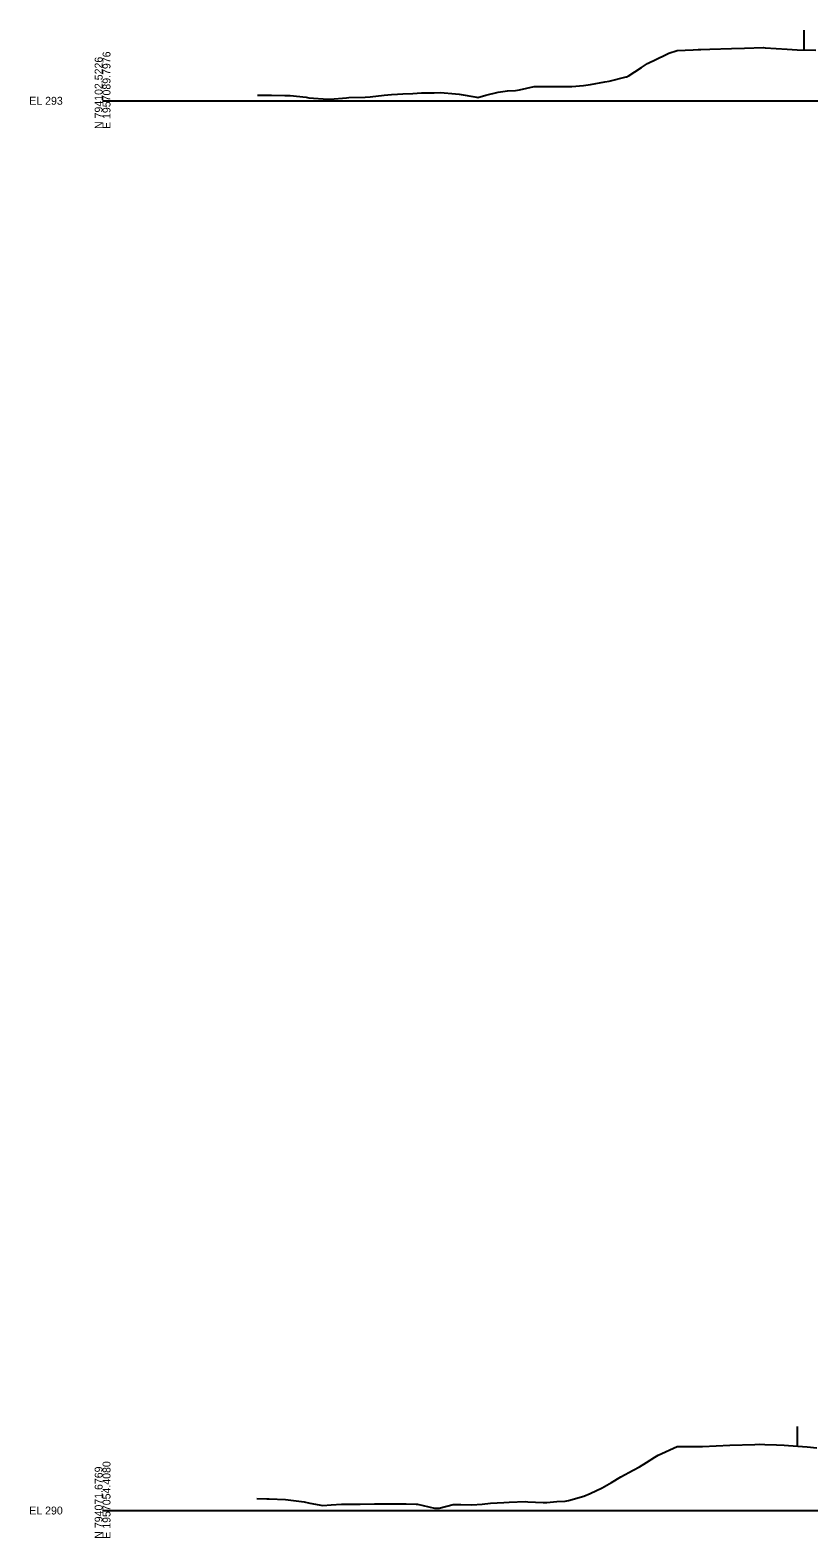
# Model space of a CAD drawing. Extents: x -4026 to 9638, y -10 to 19609.
# Drawn here: x -3026 to -2750, y 7490 to 8025 of the extents above; entities that cross this region are included whole.
import ezdxf

# ---------------------------------------------------------------- set-up
doc = ezdxf.new("R2010")
doc.units = 0
for name, color, linetype in [('Default', 7, 'Continuous'), ('RD_EX_Fence_Other', 7, 'Continuous'), ('RD_GPK_XS_Cell', 7, 'Continuous'), ('RD_XS_ExGround', 7, 'Continuous')]:
    doc.layers.add(name, color=color, linetype=linetype)

msp = doc.modelspace()

# ---------------------------------------------------------------- linework, layer by layer
at = {"layer": 'RD_EX_Fence_Other'}
for p, q in [((-2751.25, 8025.05), (-2751.25, 8018.05)), ((-2753.59, 7529.81), (-2753.59, 7522.81))]:
    msp.add_line(p, q, dxfattribs=at)
at = {"layer": 'RD_GPK_XS_Cell'}
for p, q in [((-3000, 8000), (-2650, 8000)), ((-3000, 7500), (-2650, 7500))]:
    msp.add_line(p, q, dxfattribs=at)
at = {"layer": 'RD_XS_ExGround'}
for points in [[(-2945, 8002.01), (-2942.98, 8001.98), (-2940.11, 8001.96), (-2935.41, 8001.86), (-2933.46, 8001.84), (-2927.84, 8001.26), (-2927.28, 8001.16), (-2926.8, 8001.04), (-2920.14, 8000.55), (-2919.23, 8000.62), (-2913.48, 8001.08), (-2912.69, 8001.12), (-2906.82, 8001.23), (-2905.12, 8001.35), (-2900.17, 8001.94), (-2897.55, 8002.17), (-2895.4, 8002.29), (-2893.51, 8002.41), (-2889.98, 8002.63), (-2886.85, 8002.83), (-2882.4, 8002.84), (-2880.19, 8002.92), (-2874.83, 8002.5), (-2873.53, 8002.31), (-2867.26, 8001.27), (-2866.88, 8001.22), (-2864.07, 8001.94), (-2859.69, 8003), (-2856.43, 8003.53), (-2853.56, 8003.67), (-2852.12, 8003.94), (-2846.9, 8005.08), (-2844.55, 8005.1), (-2840.24, 8005.08), (-2836.97, 8005.03), (-2833.59, 8005.07), (-2829.4, 8005.44), (-2826.93, 8005.74), (-2821.83, 8006.67), (-2820.27, 8006.97), (-2814.26, 8008.45), (-2813.91, 8008.54), (-2813.61, 8008.68), (-2808.9, 8011.84), (-2806.69, 8013.28), (-2800.29, 8016.35), (-2799.11, 8016.84), (-2796.2, 8017.86), (-2790.5, 8018.12), (-2788.71, 8018.14), (-2787.81, 8018.16), (-2784.66, 8018.26), (-2776.89, 8018.5), (-2772.33, 8018.64), (-2765.57, 8018.87), (-2764.97, 8018.82), (-2757.23, 8018.34), (-2753.68, 8018.09), (-2747.03, 8017.98)], [(-2945.29, 7504.23), (-2941.69, 7504.14), (-2940.89, 7504.11), (-2935.08, 7503.92), (-2934.16, 7503.81), (-2928.47, 7503.03), (-2926.51, 7502.55), (-2921.86, 7501.73), (-2918.87, 7502.02), (-2915.26, 7502.24), (-2913.38, 7502.26), (-2911.22, 7502.21), (-2909.84, 7502.23), (-2908.65, 7502.29), (-2903.57, 7502.35), (-2902.04, 7502.37), (-2895.92, 7502.38), (-2895.43, 7502.38), (-2892.32, 7502.33), (-2888.82, 7502.29), (-2888.27, 7502.28), (-2882.22, 7500.83), (-2880.63, 7500.78), (-2875.61, 7502.19), (-2872.98, 7502.13), (-2869, 7502), (-2865.33, 7502.29), (-2862.39, 7502.57), (-2857.68, 7502.84), (-2855.79, 7502.95), (-2850.03, 7503.15), (-2849.18, 7503.13), (-2843.76, 7502.86), (-2842.38, 7502.81), (-2838.94, 7503.15), (-2835.96, 7503.37), (-2834.74, 7503.58), (-2829.36, 7505.04), (-2827.09, 7505.99), (-2822.75, 7508.02), (-2819.44, 7509.98), (-2816.14, 7511.99), (-2811.79, 7514.29), (-2809.53, 7515.45), (-2807.04, 7517.03), (-2804.14, 7518.89), (-2802.93, 7519.64), (-2796.17, 7522.72), (-2795.72, 7522.71), (-2788.65, 7522.69), (-2787.21, 7522.75), (-2777.55, 7523.16), (-2768.6, 7523.44), (-2766.89, 7523.5), (-2765.14, 7523.47), (-2760.95, 7523.32), (-2758.26, 7523.13), (-2756.67, 7523.02), (-2750.07, 7522.54), (-2746.62, 7522.28)]]:
    msp.add_lwpolyline(points, dxfattribs=at)

# ---------------------------------------------------------------- texts
at = {"layer": 'Default'}
for p in [(-3000, 8000), (-3000, 7500)]:
    msp.add_text('-', height=0.0001, dxfattribs=at).set_placement(p)
at = {"layer": 'RD_GPK_XS_Cell'}
for s, p in [('E 1957089.7976', (-2997.2, 7990)), ('N 794102.5226', (-3000, 7990)), ('N 794071.6769', (-3000, 7490)), ('E 1957054.4080', (-2997.2, 7490))]:
    msp.add_text(s, height=2.8, rotation=90, dxfattribs=at).set_placement(p)
for s, p in [('EL 293', (-3026, 7998.6)), ('EL 290', (-3026, 7498.6))]:
    msp.add_text(s, height=2.8, dxfattribs=at).set_placement(p)

doc.saveas('drawing.dxf')
